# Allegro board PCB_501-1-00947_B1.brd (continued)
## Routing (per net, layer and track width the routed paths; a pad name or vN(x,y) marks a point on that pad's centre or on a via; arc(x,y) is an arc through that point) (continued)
DRAM_ADDR3: length 56.1
  TOP w0.102: U7.AC20 v2(62.59,95.84)
  TOP w0.137: U8.N2 v2(72.11,113.22) ; v2(54.95,113.22) 55.35,112.82 U9.N2
  L6_INT_2 w0.137: v2(54.95,113.22) 55.35,113.22 55.46,113.11 55.61,113.11 55.75,113.25 55.75,113.39 55.68,113.46 55.68,113.56 55.86,113.74 56.01,113.74 56.15,113.6 56.15,113.46 56.36,113.24 56.5,113.24 56.64,113.38 56.64,113.49 56.54,113.59 56.54,113.73 56.24,114.03 56.24,114.12 56.23,114.13 56.39,114.29 56.58,114.29 56.85,114.02 57.53,114.02 57.8,113.75 57.8,113.53 57.95,113.38 60.24,113.38 60.44,113.59 60.44,114.11 60.83,114.5 61.1,114.5 61.4,114.21 61.57,114.21 61.86,114.5 62.63,114.5 62.75,114.38 62.75,114.23 v2(62.91,114.06) 63.41,114.56 63.55,114.56 63.83,114.84 63.83,115.21 65.2,116.57 67.66,116.57 68.21,116.02 68.44,116.02 70.83,113.63 72,113.63 72.11,113.52 v2(72.11,113.22)
  BOTTOM w0.137: v2(62.59,95.84) 63.02,96.28 63.02,96.59 63.37,96.94 63.37,98.05 62.59,98.82 62.59,99.65 62.23,100.01 62.23,100.74 63.01,101.52 63.01,101.88 62.58,102.31 62.22,102.31 62.08,102.44 62.08,103.05 62.36,103.33 62.36,103.51 63.03,104.18 63.71,104.18 64.08,104.54 64.08,108.25 63.71,108.63 63.71,108.73 63.22,109.21 63.22,109.56 62.81,109.97 62.81,110.69 62.23,111.26 62.23,111.54 62.57,111.87 62.57,113.11 61.77,113.91 61.44,113.91 60.91,113.37 60.54,113.37 59.22,114.7 59.22,114.88 59.4,115.06 59.65,115.06 60.28,114.43 60.6,114.43 61.1,114.93 61.35,114.93 62.27,114.02 62.86,114.02 v2(62.91,114.06)
DRAM_ADDR4: length 61.1
  TOP w0.102: U7.AB21 v2(61.53,95.84)
  TOP w0.137: U9.P8 50.14,114.02 50.14,114.58 49.91,114.81 49.9,114.81 49.89,114.82 49.57,114.82 49.32,115.08 49.32,116.42 53.13,120.23 v2(61.23,120.23) 61.9,120.23 62.43,119.7 62.89,119.7 63.07,119.88 63.07,120.13 63.23,120.29 63.42,120.29 63.66,120.05 63.92,120.05 64.15,120.28 64.34,120.28 64.6,120.02 64.83,120.02 65.11,120.29 65.37,120.29 65.48,120.18 65.48,119.84 65.34,119.69 65.34,119.46 66.19,118.61 66.35,118.61 66.76,119.03 66.93,119.03 67.1,118.85 67.1,118.38 67.28,118.2 67.75,118.2 69.63,116.32 69.63,114.81 69.53,114.7 69.1,114.7 68.99,114.59 68.99,114.16 68.85,114.02 68.33,114.02 67.92,113.62 U8.P8
  L3_INT_1 w0.137: v2(61.23,120.23) 61.98,119.48 61.98,114.44 61.03,113.49 61.03,113.14 61.53,112.63 61.53,112.08 61.48,112.02 61.48,112.01 61.3,111.83 61.21,111.83 60.88,111.49 60.88,109.42 61.95,108.36 61.95,105.4 62.47,104.87 62.47,102.92 61.96,102.41 61.59,102.04 61.59,100.87 62.13,100.33 62.13,96.97 61.53,96.37 v2(61.53,95.84)
DRAM_ADDR5: length 57.8
  TOP w0.102: U7.Y23 v2(59.4,95.84)
  TOP w0.137: U8.P2 v2(72.11,114.02) ; U9.P2 v2(54.95,114.02)
  L3_INT_1 w0.137: v2(59.4,95.84) 59.4,96.55 59.92,97.07 59.92,99.89 59.8,100.01 59.63,100.01 59.51,99.89 59.51,97.43 59.39,97.31 59.22,97.31 59.1,97.43 59.1,100.05 59.45,100.4 59.72,100.4 59.92,100.6 59.92,102.15 60.15,102.37 60.15,102.55 59.86,102.84 59.86,103.35 60.09,103.58 60.09,103.77 59.78,104.07 59.78,104.27 60,104.48 60,104.66 59.88,104.78 59.83,104.78 59.71,104.9 59.71,105.07 59.83,105.19 59.88,105.19 60,105.31 60,105.48 59.88,105.6 59.83,105.6 59.71,105.72 59.71,105.89 59.83,106.01 59.88,106.01 60,106.13 60,106.4 59.89,106.51 59.89,106.65 59.77,106.76 59.77,106.96 60.02,107.2 60.02,107.46 59.75,107.73 59.75,108.41 59.89,108.55 59.89,108.75 59.71,108.94 59.71,112.04 59.87,112.21 59.87,112.69 59.71,112.85 59.71,114.5 60.15,114.94 60.15,114.95 60.23,115.03 v2(60.23,115.18)
  L6_INT_2 w0.137: v2(54.95,114.02) 55.21,114.02 56.04,114.84 56.27,114.84 56.39,114.96 56.39,115.16 56.06,115.49 56.06,115.87 56.16,115.97 56.38,115.97 56.64,115.71 56.78,115.71 56.94,115.87 56.94,116.01 56.72,116.23 56.72,116.41 56.87,116.55 57.02,116.55 57.26,116.31 57.48,116.31 57.56,116.4 57.56,116.51 57.67,116.62 57.83,116.62 58,116.44 58,115.87 57.45,115.32 57.45,115.18 57.56,115.07 57.76,115.07 58.07,115.38 58.2,115.38 58.3,115.29 58.3,115 57.96,114.66 57.96,114.52 58.07,114.4 58.24,114.4 58.46,114.63 58.66,114.63 58.8,114.49 58.8,114.3 58.93,114.17 59.37,114.17 59.5,114.3 59.5,114.5 59.37,114.63 59.27,114.63 59.15,114.75 59.15,114.89 59.32,115.06 59.71,115.06 59.9,114.88 60.09,114.88 60.23,115.01 v2(60.23,115.18) 60.33,115.28 62.06,115.28 64.14,117.36 68.13,117.36 70.96,114.52 71.6,114.52 v2(72.11,114.02)
DRAM_ADDR6: length 58.6
  TOP w0.102: U7.V22 v2(58.87,94.25)
  TOP w0.137: U8.R8 67.9,114.42 68.09,114.61 68.3,114.82 68.67,114.82 69.22,115.37 69.22,116.16 69.1,116.27 68.91,116.27 68.67,116.04 68.48,116.04 68.26,116.25 68.26,116.45 68.45,116.64 68.45,116.95 67.63,117.77 67.07,117.77 66.63,118.2 66.05,118.2 64.64,119.6 63.38,119.6 63.1,119.31 62.22,119.31 61.74,119.8 v2(60.59,119.8) 53.25,119.8 50.17,116.71 50.17,116.65 50.16,116.65 50.16,115.38 50.16,115.38 50.16,115.05 50.55,114.66 U9.R8
  L3_INT_1 w0.137: v2(60.59,119.8) 60.46,119.8 60.04,119.37 59.88,119.01 59.88,118.51 59.44,117.56 59.44,117.34 58.97,116.86 58.55,116.62 58.39,116.46 58.39,116.23 58.26,115.72 57.76,115.22 56.77,114.76 56.09,114.08 56.09,110 56.44,109.65 56.9,109.65 58,108.56 58,102.81 57.24,102.05 57.24,95.36 58.35,94.25 v2(58.87,94.25)
DRAM_ADDR7: length 59
  TOP w0.137: U9.R2 55.35,114.47 v2(54.98,114.84) ; U8.R2 v2(72.11,114.82) ; v2(59.93,95.31) U7.Y22
  L3_INT_1 w0.137: v2(59.68,115.88) 59.68,115.9 59.88,116.1 60.21,116.1 60.3,116.01 60.3,115.74 60.16,115.6 60.05,115.6 60.05,115.6 60.04,115.6 59.79,115.35 59.79,115.14 59.31,114.66 59.31,111.24 59.17,111.09 59.03,111.09 58.89,111.23 58.89,112.85 58.75,113 58.56,113 58.44,112.87 58.44,109.85 59.19,109.1 59.19,102.16 58.44,101.41 58.44,96.28 59.4,95.31 v2(59.93,95.31)
  L6_INT_2 w0.137: v2(54.98,114.84) 55.43,115.29 55.43,115.9 55.05,116.28 54.83,116.28 54.62,116.06 54.4,116.06 54.23,116.24 54.23,116.43 54.81,117.01 55.11,117.01 55.56,116.56 55.76,116.56 56.41,117.21 56.41,117.39 56.24,117.57 56.05,117.57 55.81,117.33 55.62,117.33 55.47,117.48 55.47,117.67 55.93,118.13 57.02,118.13 57.67,117.48 58.12,117.48 58.75,116.85 59,116.85 59.4,117.26 59.6,117.26 59.9,116.96 59.9,116.77 59.73,116.6 59.39,116.6 59.27,116.48 59.27,116.07 59.46,115.88 v2(59.68,115.88) 59.86,116.06 61.73,116.06 63.88,118.21 68.5,118.21 71.2,115.51 71.42,115.51 v2(72.11,114.82)
DRAM_ADDR8: length 55.5
  TOP w0.102: U7.W22 v2(59.4,94.78)
  TOP w0.137: U9.T8 50.55,116.49 53.36,119.3 60.13,119.3 v2(60.37,119.06) 60.53,118.9 63.56,118.9 64.27,118.19 64.47,118.19 64.59,118.31 64.59,118.45 64.14,118.9 64.14,119.14 64.21,119.21 64.48,119.21 65.88,117.81 66.47,117.81 66.9,117.38 67.47,117.38 67.81,117.04 67.81,116.2 68.04,115.97 68.04,115.55 U8.T8
  L3_INT_1 w0.137: v2(60.37,119.06) 60.37,118.79 60.53,118.63 60.53,118.5 60.2,118.17 60.2,117.53 59.36,116.69 59.36,116.22 59.19,116.05 59.19,115.11 58.89,114.81 58.89,113.6 58.68,113.39 58.52,113.39 58.23,113.68 58.23,113.85 58.47,114.09 58.47,114.49 58.38,114.57 58.24,114.57 57.92,114.25 57.92,114.16 57.61,113.84 57.61,113.65 58.05,113.21 58.05,112.49 57.71,112.15 57.71,111.72 58.05,111.38 58.05,110.15 57.92,110.03 57.92,109.81 58.8,108.93 58.8,102.32 58.05,101.57 58.05,95.6 58.87,94.78 v2(59.4,94.78)
DRAM_ADDR9: length 58.5
  TOP w0.102: U7.V23 v2(58.34,94.78)
  TOP w0.137: U8.R3 v2(71.12,115) ; U9.R3 v2(54.15,114.82)
  L3_INT_1 w0.137: v2(58.34,94.78) 57.64,95.49 57.64,101.9 57.74,102.01 57.74,102.02 58.41,102.68 58.41,108.74 57.12,110.03 57.12,110.21 56.81,110.52 56.53,110.52 56.45,110.6 56.45,110.84 56.54,110.93 57.35,110.93 57.51,111.09 57.51,111.3 57.34,111.48 56.62,111.48 56.45,111.65 56.45,112.27 56.59,112.42 57.45,112.42 57.58,112.55 57.58,113.01 57.38,113.22 56.58,113.22 56.43,113.36 56.43,113.76 56.69,114.02 57.31,114.02 57.58,114.29 57.58,114.47 58.4,115.29 v2(58.77,115.29)
  L6_INT_2 w0.137: v2(54.15,114.82) 53.69,114.82 53.45,114.57 52.95,114.57 52.23,115.29 52.05,115.29 51.32,114.56 51.32,114.37 51.46,114.23 51.64,114.23 52.06,114.66 52.26,114.66 52.77,114.14 53.67,114.14 53.94,114.42 55.19,114.42 55.75,114.98 55.75,116 56.77,117.02 57.98,117.02 58.37,116.63 58.37,116.08 58.77,115.69 v2(58.77,115.29) 58.93,115.45 59.9,115.45 60.12,115.67 61.89,115.67 63.99,117.77 68.35,117.77 v2(71.12,115)
DRAM_ADDR10: length 57.6
  TOP w0.102: U7.T23 57.28,93.72 v2(57.28,93.72)
  TOP w0.137: U8.L7 68.09,110.79 66.03,110.79 63.98,112.85 63.39,112.85 60.59,115.65 60.1,115.65 59.22,114.77 57.92,114.77 57.37,115.33 v2(57.37,115.9) 57.69,115.9 57.82,115.78 57.82,115.52 57.97,115.36 58.16,115.36 58.35,115.56 58.35,116.25 58.22,116.39 57,116.39 56.86,116.25 56.86,115.83 56.65,115.61 56.49,115.61 56.34,115.76 56.34,116.14 56.08,116.41 55.89,116.41 55.75,116.26 55.57,116.26 55.39,116.44 53.83,116.44 53.34,115.95 53.34,114.03 53.11,113.8 53.11,113.51 53.27,113.35 53.27,113.14 U9.L7
  L3_INT_1 w0.137: v2(57.28,93.72) 57.03,93.98 56.34,93.98 56.06,94.26 56.06,94.69 56.43,95.07 56.43,102.32 57.2,103.09 57.2,108.06 57.04,108.22 56.4,108.22 55.41,109.2 55.41,116.37 55.62,116.58 56.31,116.58 56.43,116.46 56.43,116.35 56.55,116.23 56.72,116.23 56.84,116.35 56.84,116.46 56.96,116.58 57.23,116.58 57.37,116.45 v2(57.37,115.9)
DRAM_ADDR11: length 54.7
  TOP w0.102: v2(58.34,93.72) 58.34,93.19 U7.U22
  TOP w0.137: U8.R7 68.31,114.42 67.91,114.02 66.75,114.02 65.72,115.05 65.72,115.77 64.09,117.41 63.95,117.41 63.32,118.04 61.14,118.04 61.14,118.04 60.79,118.04 60.79,118.04 60.04,118.04 v2(59.43,118.65) 59.31,118.78 53.52,118.78 51.46,116.71 51.46,116.06 51.78,115.75 51.78,114.84 U9.R7
  L3_INT_1 w0.137: v2(59.43,118.65) 58.94,118.16 58.94,117.96 59.05,117.85 59.05,117.5 58.81,117.25 58.18,117.25 57.89,116.96 57.89,115.83 57.55,115.49 57.19,115.49 56.87,115.81 56.4,115.81 56.13,116.08 55.92,116.08 55.79,115.94 55.79,109.33 56.5,108.61 57.19,108.61 57.58,108.22 57.58,103.04 56.85,102.31 56.85,94.69 57.81,93.72 v2(58.34,93.72)
DRAM_ADDR12: length 55.7
  TOP w0.102: U7.T22 v2(57.81,93.19)
  TOP w0.137: U8.N7 68.12,113.21 66.36,113.21 65.77,113.8 65.57,113.8 65.23,114.14 65.23,114.75 62.33,117.65 61.3,117.65 60.63,117.65 58.65,117.65 v2(58.63,117.68) 58.26,117.68 58.16,117.58 57.6,117.58 57.36,117.83 57.36,118.19 57.16,118.39 53.69,118.38 51.92,116.62 51.92,116.17 52.12,115.97 52.12,114.55 51.78,114.21 51.78,113.25 U9.N7
  L3_INT_1 w0.137: v2(57.81,93.19) 57.28,93.19 56.92,93.55 56.92,93.55 56.91,93.56 56.28,93.56 55.61,94.24 55.61,94.74 56.02,95.16 56.02,102.81 56.16,102.95 56.16,107.81 55.11,108.86 54.74,108.86 54.28,109.33 54.28,109.47 54.55,109.75 54.55,116.07 55.5,117.02 57.24,117.02 57.8,117.58 57.96,117.58 58.24,117.87 58.44,117.87 v2(58.63,117.68)
DRAM_ADDR13: length 57
  TOP w0.102: U7.P23 v2(56.22,92.66)
  TOP w0.137: U8.T3 71.36,115.57 v2(71.36,116.03) ; U9.T3 v2(54.15,115.62)
  L6_INT_2 w0.137: v2(54.15,115.62) 53.91,115.86 53.77,115.86 53.4,115.49 53.22,115.49 53.06,115.65 53.06,115.81 55.77,118.52 58.41,118.52 59.28,117.65 59.86,117.65 60.98,116.53 v2(61.55,116.53) 63.62,118.6 68.79,118.6 71.36,116.03 v2(71.36,116.03)
  BOTTOM w0.137: v2(61.55,116.53) 61.55,117.21 60.67,118.09 59.63,118.09 57.92,116.38 57.92,115.84 57.51,115.44 57.51,111.74 57.06,111.29 57.06,109.8 58.19,108.66 58.19,102.65 56.29,100.74 56.29,94.74 55.68,94.14 55.68,93.2 v2(56.22,92.66)
DRAM_ADDR14: length 56.8
  TOP w0.102: U7.AB18 v2(63.12,94.23)
  TOP w0.137: U8.T7 68.26,115.22 67.88,114.83 67.87,114.82 67.55,114.82 67.54,114.83 67.53,114.83 67.31,115.05 67.31,115.59 67.53,115.81 67.53,116.05 67.41,116.17 67.41,116.64 67.24,116.8 67.1,116.8 66.39,116.09 66.09,116.09 65.88,116.3 65.88,116.6 66.05,116.76 66.35,116.76 66.51,116.93 66.51,117.13 66.22,117.42 65.71,117.42 65.11,118.02 64.85,118.02 64.63,117.8 64.11,117.8 63.45,118.47 v2(60.96,118.47) ; U9.T7 v2(50.95,114.81)
  L6_INT_2 w0.137: v2(50.95,114.81) 55.45,119.31 59.49,119.31 60.33,118.47 v2(60.96,118.47)
  BOTTOM w0.137: v2(63.12,94.23) 63.12,94.78 63.8,95.46 63.8,95.84 64.35,96.4 64.35,98.18 65.02,98.84 65.02,109.26 64.21,110.07 64.21,110.55 63.56,111.2 63.56,112.62 64.21,113.26 64.21,114.14 63.83,114.52 63.14,114.52 63.13,114.52 62.32,114.52 61.46,115.38 61.05,115.38 60.53,115.9 60.53,116.05 60.83,116.35 61.01,116.35 61.44,115.92 61.7,115.92 62.14,116.37 62.14,117.29 v2(60.96,118.47)
DRAM_ADDR15: length 56
  TOP w0.102: U7.AB20 62.06,95.3 62.04,95.31 62.04,95.32 v2(62.05,95.32)
  TOP w0.137: U8.M7 68.26,112.02 67.86,111.61 65.99,111.61 64.46,113.13 64.46,114.4 64.02,114.84 63.85,114.84 63.53,114.52 63.17,114.52 62.92,114.77 62.92,115.24 62.69,115.46 62.69,116.07 62.55,116.21 62.14,116.21 62,116.07 62,115.83 61.87,115.7 61.66,115.7 61.03,116.34 60.45,116.34 v2(60.26,116.53) 60.01,116.78 56.32,116.78 56.28,116.83 53.67,116.83 52.95,116.11 52.95,114.23 52.54,113.82 52.54,112.83 51.72,112.02 U9.M7
  L3_INT_1 w0.137: v2(60.26,116.53) 60.08,116.71 60.08,116.85 60.28,117.05 60.42,117.05 60.74,116.74 60.74,116.12 60.89,115.97 60.89,115.85 60.69,115.65 60.69,114.93 60.1,114.34 60.1,113.01 60.26,112.85 60.26,112.04 60.1,111.88 60.1,109.1 60.45,108.75 60.45,108.55 60.14,108.25 60.14,107.9 60.57,107.46 60.57,107.19 60.28,106.89 60.28,106.67 60.57,106.37 60.57,106.14 60.39,105.95 60.39,104.44 60.73,104.09 60.73,103.78 61.04,103.47 61.25,103.47 61.43,103.29 61.43,103.19 61.15,102.91 60.95,102.91 60.53,103.33 60.39,103.33 60.25,103.19 60.25,103 60.76,102.49 60.76,102.26 60.62,102.12 60.45,102.12 60.31,101.98 60.31,101.71 60.45,101.57 60.62,101.57 60.76,101.43 60.76,101.16 60.62,101.02 60.45,101.02 60.31,100.89 60.31,100.61 60.45,100.47 60.62,100.47 60.76,100.34 60.76,100.06 60.62,99.93 60.45,99.93 60.31,99.79 60.31,99.51 60.45,99.38 60.53,99.38 60.67,99.24 60.67,99.01 60.53,98.88 60.36,98.88 60.22,98.74 60.22,98.49 60.36,98.35 60.65,98.35 60.82,98.19 60.82,97.95 60.68,97.82 60.55,97.82 60.37,97.64 60.37,97.53 60.84,97.06 60.84,96.74 60.62,96.52 60.62,96.22 61.52,95.32 v2(62.05,95.32)
DRAM_CAS_B: length 53.7
  TOP w0.104: U7.AC14 v2(65.77,92.66)
  TOP w0.137: U8.K3 v2(71.31,110.82) ; U9.K3 v2(54.15,110.82)
  L3_INT_1 w0.137: v2(65.77,92.66) 65.77,93.52 65.49,93.81 65.49,95.75 64.82,96.42 64.82,101.75 65.56,102.49 65.56,105.81 65.77,106.02 65.77,108.48 66.9,109.61 66.9,112.23 66.54,112.58 66.33,112.58 66.17,112.74 66.17,113.42 65.81,113.78 65.27,113.78 65.07,113.98 65.07,114.23 65.23,114.39 65.23,114.62 65.02,114.84 65.02,115.15 65.23,115.36 65.23,115.59 65.1,115.72 64.63,115.72 64.5,115.59 64.5,111.16 v2(63.36,110.02)
  L6_INT_2 w0.137: v2(54.15,110.82) U9.K3 55.83,110.42 55.95,110.53 56.88,110.53 57.35,110.07 57.6,110.07 57.89,109.78 60.45,109.78 60.53,109.85 62.8,109.85 62.97,110.02 v2(63.36,110.02) 64.1,110.77 64.49,110.77 65.33,111.61 66.58,111.61 66.83,111.86 66.83,112.14 67.04,112.35 67.35,112.35 67.73,111.97 68.27,111.97 69.04,111.2 69.8,111.2 70.19,110.82 v2(71.31,110.82)
DRAM_CS0_B: length 56.1
  TOP w0.137: U7.AB23 v2(60.46,96.9) ; U8.L2 v2(72.11,111.62) ; v2(54.95,111.62) 55.51,111.62 55.75,111.38 55.75,110.87 55.66,110.78 55.52,110.78 55.35,110.95 U9.L2
  L6_INT_2 w0.137: v2(72.11,111.62) 71.71,112.02 70.39,112.02 68.85,113.55 65.45,113.55 64.02,112.12 62.8,112.12 62.3,111.61 61.69,111.61 v2(61.41,111.34) 60.94,111.81 58.44,111.81 58.32,111.68 58.32,111.5 58.43,111.39 59.15,111.39 59.29,111.26 59.29,111.12 59.15,110.98 58.23,110.98 57.96,111.25 57.96,111.66 57.88,111.74 57.76,111.74 57.24,111.21 56.74,111.21 56.24,111.72 56.04,111.72 55.95,111.63 55.95,111.37 55.81,111.23 55.57,111.23 55.43,111.38 55.43,111.51 55.3,111.64 54.98,111.64 v2(54.95,111.62)
  BOTTOM w0.137: v2(60.46,96.9) 59.76,96.9 58.17,95.32 57.91,95.32 57.49,95.73 57.49,99.85 59.7,102.05 59.7,109.08 58.78,110 58.78,111.61 59.48,112.3 59.67,112.3 59.81,112.17 59.81,111.97 59.25,111.41 59.25,111.22 59.44,111.02 59.64,111.02 60.22,111.6 60.41,111.6 60.56,111.46 60.56,111.26 59.91,110.61 59.51,110.21 59.51,110.02 59.71,109.82 59.9,109.82 v2(61.41,111.34)
DRAM_CS1_B: length 57.2
  TOP w0.102: U7.AA22 v2(60.46,95.84)
  TOP w0.137: U9.L1 56.52,111.22 56.54,111.2 57.83,111.2 58.12,111.48 58.12,112.69 57.98,112.83 57.64,112.83 57.47,112.99 57.47,113.46 57.75,113.73 58.57,113.73 58.7,113.61 58.7,111.45 57.73,110.48 v2(57.56,110.48) ; U8.L1 v2(72.91,111.62)
  L6_INT_2 w0.137: v2(72.91,111.62) 72.91,111.6 72.52,111.21 70.29,111.21 68.68,112.83 66.53,112.83 65.84,112.13 65.18,112.13 64.36,111.31 63.29,111.31 62.81,110.83 62.13,110.83 61.75,110.44 v2(61.32,110.44) 61.05,110.44 60.51,110.99 60.27,110.99 59.46,110.17 57.87,110.17 v2(57.56,110.48)
  BOTTOM w0.137: v2(61.32,110.44) 60.1,109.22 60.1,109 60.28,108.82 60.41,108.82 61.81,110.22 61.9,110.22 62.15,109.97 62.15,109.83 60.88,108.56 60.88,108.38 61.1,108.16 61.3,108.16 61.43,108.29 61.68,108.29 61.99,107.98 61.99,107.71 61.87,107.6 61.87,107.43 62,107.31 62.19,107.31 62.31,107.19 62.31,107.02 62.19,106.9 62,106.9 61.87,106.78 61.87,106.61 62,106.49 62.19,106.49 62.31,106.37 62.31,106.2 62.19,106.08 62,106.08 61.87,105.96 61.87,105.79 62,105.67 62.19,105.67 62.31,105.54 62.31,104.68 62.04,104.41 61.78,104.41 61.58,104.2 61.58,103.78 61.33,103.53 60.98,103.53 60.74,103.29 60.74,102.79 60.86,102.67 61.18,102.67 61.3,102.55 61.3,102.38 61.18,102.26 60.86,102.26 60.74,102.14 60.74,101.63 60.35,101.23 60.35,100.73 60.56,100.51 60.56,100.1 60.44,99.97 60.44,99.52 60.82,99.15 60.82,98.82 60.46,98.47 60.46,97.99 60.59,97.86 60.77,97.86 61.05,98.14 61.05,98.32 61.23,98.5 61.37,98.5 61.55,98.32 61.55,98.03 61.35,97.83 61.35,97.69 61.52,97.53 61.66,97.53 61.96,97.83 62.14,97.83 62.38,97.6 62.38,97.39 62.04,97.04 62.04,96.89 60.99,95.84 v2(60.46,95.84)
DRAM_DATA0: length 13.5
  TOP w0.137: U8.D7 68.59,105.69 68.87,105.69 69.01,105.56 69.01,105.38 68.87,105.24 68.66,105.24 68.37,105.24 68.1,104.97 68.1,103.82 67.9,103.62 66.53,103.62 65.83,102.92 65.83,102.52 66.13,102.22 66.13,102.11 63.11,99.09 63.11,98.5 62.06,97.44 U7.AD22
DRAM_DATA1: length 11.8
  TOP w0.137: U8.C8 67.31,105.22 66.11,105.22 64.46,103.56 64.46,103.02 64.91,102.58 64.91,102.29 63.3,100.68 63.3,100.38 62.3,99.37 62.3,98.74 61.98,98.42 61.53,97.96 U7.AD23 arc(61.53,97.43) 61.52,97.43
DRAM_DATA2: length 13.1
  TOP w0.137: 70.46,103.57 70.46,102.59 68.13,100.26 67.53,100.26 U7.AE20 ; 70.46,103.57 71.15,104.26 ; 70.46,103.57 71.15,104.26 ; 71.15,104.26 U8.C3
DRAM_DATA3: length 11.7
  TOP w0.137: U7.AE23 62.7,98.61 62.7,99.27 63.67,100.24 63.67,100.52 63.81,100.67 64.1,100.67 64.25,100.82 64.25,101.11 64.4,101.25 64.68,101.25 64.83,101.4 64.83,101.69 64.98,101.83 65.26,101.83 65.48,102.05 65.48,102.61 64.93,103.16 64.93,103.31 65.23,103.62 65.38,103.62 65.59,103.4 65.77,103.4 65.95,103.59 65.95,103.73 65.72,103.96 65.72,104.14 65.99,104.41 67.32,104.41 U8.B8
DRAM_DATA4: length 11.9
  TOP w0.137: U8.A7 68.78,103.22 68.92,103.35 68.92,103.54 68.84,103.62 68.35,103.62 68.11,103.38 68.11,103.02 68.25,102.88 68.25,102.68 67.91,102.34 67.91,102.14 67.81,102.04 67.35,102.04 66.89,102.5 66.74,102.5 66.54,102.31 66.54,102.2 66.76,101.98 66.76,101.8 66.61,101.66 66.16,101.66 65.63,101.14 65.63,100.99 65.47,100.82 65.32,100.82 64.8,100.3 64.8,100.14 64.64,99.98 64.48,99.98 63.59,99.1 63.59,98.44 U7.AE22
DRAM_DATA5: length 12
  TOP w0.137: U8.A3 71.15,103.22 70.8,102.86 70.8,102.31 68.32,99.83 67.63,99.83 64.84,97.04 63.65,95.84 U7.AD19
DRAM_DATA6: length 12.4
  TOP w0.137: U7.AD18 64.18,95.33 65.9,97.05 TP15.1 67.96,99.07 68.8,99.07 TP16.1 72.51,102.78 U8.A2
DRAM_DATA7: length 12.9
  TOP w0.137: U7.AE19 67.78,99.45 68.57,99.45 72.12,102.99 72.12,104.42 U8.C2
DRAM_DATA8: length 18
  TOP w0.137: U8.E3 71.36,106.07 v2(71.29,106.07) ; v2(70.15,96.9) 70.15,96.37 68.47,94.68 68.32,94.68 67.94,94.31 U7.AE14
  L3_INT_1 w0.137: v2(70.15,96.9) 69.82,97.23 69.82,97.9 69.94,98.02 70.18,98.02 70.3,98.14 70.3,98.31 70.18,98.43 69.94,98.43 69.82,98.55 69.82,98.81 70.06,99.05 70.23,99.05 70.4,98.89 70.57,98.89 70.69,99.01 70.69,99.18 70.52,99.34 70.52,99.51 70.64,99.64 70.82,99.64 70.98,99.47 71.15,99.47 71.27,99.59 71.27,99.76 71.11,99.93 71.11,100.1 71.37,100.36 71.37,102.95 71.77,103.35 71.77,104.02 71.29,104.5 v2(71.29,106.07)
DRAM_DATA9: length 18.1
  TOP w0.137: v2(68.1,108.4) 68.1,108.42 U8.H8 ; v2(65.68,96.22) 64.77,95.31 U7.AE18
  L3_INT_1 w0.137: v2(65.68,96.22) 65.68,97 66.01,97.34 66.01,100.05 66.25,100.29 67.4,100.29 67.65,100.54 67.65,101.42 67.53,101.54 66.98,101.54 66.86,101.66 66.86,101.83 66.98,101.95 67.53,101.95 67.67,102.09 67.67,102.92 67.39,103.21 66.93,103.21 66.8,103.34 66.8,107.05 66.77,107.07 v2(68.1,108.4)
DRAM_DATA10: length 17.8
  TOP w0.137: U7.AE17 65.24,95.12 66.38,96.26 66.38,96.72 v2(66.39,96.72) ; U8.F8 v2(67.32,106.83)
  L3_INT_1 w0.137: v2(66.39,96.72) 66.38,96.73 66.38,99.61 66.52,99.75 66.86,99.75 67,99.6 67,98.36 67.15,98.21 67.35,98.21 67.52,98.39 67.52,99.8 68.36,100.64 68.36,100.93 68.02,101.27 68.02,103.07 67.19,103.9 67.19,106.69 v2(67.32,106.83)
DRAM_DATA11: length 17.9
  TOP w0.137: v2(66.96,95.28) 66.96,94.91 65.77,93.72 U7.AD16 arc(65.24,93.72) 65.24,93.72 ; U8.H7 v2(69,108.33)
  L3_INT_1 w0.137: v2(69,108.33) 69.6,107.73 69.6,100.2 68.68,99.29 68.68,97.46 68.18,96.95 67.8,96.95 66.96,96.11 v2(66.96,95.28)
DRAM_DATA12: length 17.9
  TOP w0.137: U8.F7 v2(68.9,106.82) ; v2(66.26,94.91) 66.26,94.74 U7.AE16
  L3_INT_1 w0.137: v2(68.9,106.82) 69.26,106.47 69.26,106.05 69.14,105.93 68.99,105.93 68.87,105.81 68.87,105.64 68.99,105.52 69.14,105.52 69.26,105.4 69.26,105.23 69.14,105.11 68.99,105.11 68.87,104.99 68.87,104.81 68.99,104.69 69.14,104.69 69.26,104.57 69.26,104.4 69.14,104.28 68.99,104.28 68.87,104.16 68.87,103.99 68.99,103.87 69.14,103.87 69.26,103.75 69.26,103.58 69.14,103.46 68.99,103.46 68.87,103.34 68.87,103.17 68.99,103.05 69.14,103.05 69.26,102.93 69.26,102.76 69.14,102.64 68.99,102.64 68.87,102.52 68.87,102.35 68.99,102.23 69.14,102.23 69.26,102.1 69.26,101.93 69.14,101.81 68.99,101.81 68.87,101.69 68.87,101.52 68.99,101.4 69.14,101.4 69.26,101.28 69.26,100.34 68.34,99.43 68.34,97.67 68.03,97.36 67.67,97.36 66.26,95.95 v2(66.26,94.91)
DRAM_DATA13: length 19.1
  TOP w0.137: v2(70.77,97.44) 70.77,96.49 68.65,94.38 68.55,94.38 66.83,92.66 U7.AD14 ; v2(72.11,106.85) 72.11,108.41 U8.H3
  L3_INT_1 w0.137: v2(70.77,97.44) 70.77,98.53 71.81,99.57 71.81,102.86 72.11,103.17 v2(72.11,106.85)
DRAM_DATA14: length 19.2
  TOP w0.137: v2(71.93,98.59) 71.93,96.8 68.48,93.34 68.48,93.27 67.34,92.13 U7.AD13 ; U8.G2 72.88,107.64 v2(72.88,107.64)
  L3_INT_1 w0.137: v2(72.88,107.64) 73.32,107.2 73.32,103.22 72.94,102.84 72.94,99.59 v2(71.93,98.59)
DRAM_DATA15: length 18.1
  TOP w0.137: U7.AE13 71.32,96.62 v2(71.32,98.05) ; U8.F2 72.51,107.21 v2(72.91,106.81)
  L3_INT_1 w0.137: v2(71.32,98.05) 71.32,98.61 72.48,99.76 72.48,100.61 72.36,100.73 72.28,100.73 72.16,100.85 72.16,101.02 72.28,101.14 72.36,101.14 72.48,101.27 72.48,101.44 72.36,101.56 72.28,101.56 72.16,101.68 72.16,101.85 72.28,101.97 72.36,101.97 72.48,102.09 72.48,102.26 72.36,102.38 72.28,102.38 72.16,102.5 72.16,102.67 72.28,102.79 72.36,102.79 72.48,102.91 72.48,105.86 72.48,106.38 v2(72.91,106.81)
DRAM_DATA16: length 11.8
  TOP w0.137: U9.D7 52.24,104.72 52.62,104.35 53.18,103.78 53.18,102.77 58.15,97.8 58.15,97.63 U7.AA25
DRAM_DATA17: length 13
  TOP w0.137: U9.C8 50.95,104.41 50.95,103.05 50.97,103.03 50.97,102.83 50.97,102.82 50.97,102.62 55.97,97.62 55.97,97.32 57.33,95.97 57.33,95.8 57.82,95.31 U7.W24
DRAM_DATA18: length 12.3
  TOP w0.137: U7.V25 56.92,95.68 56.92,95.9 55.63,97.18 55.63,97.34 54.56,98.42 54.37,98.42 TP18.1 TP17.1 50.71,102.08 50.28,102.08 50.06,102.3 50.06,102.87 50.16,102.97 50.16,103.62 U9.B8
DRAM_DATA19: length 11.1
  TOP w0.137: U9.A7 51.35,102.86 51.56,102.66 51.91,102.66 52.05,102.52 52.05,102.1 56.56,97.59 56.56,97.46 56.5,97.4 56.5,97.23 56.62,97.11 56.79,97.11 56.87,97.2 57.04,97.2 57.16,97.08 57.16,96.91 57.08,96.82 57.08,96.65 57.2,96.53 57.37,96.53 57.46,96.61 57.63,96.61 57.81,96.43 U7.W25
DRAM_DATA20: length 11.1
  TOP w0.137: U9.A2 55.75,103.62 55.75,104.23 55.94,104.42 56.58,104.42 56.58,104.42 56.94,104.42 57.17,104.19 57.17,103.01 56.8,102.64 56.8,102.37 57.13,102.04 57.42,102.04 57.57,101.89 57.57,101.6 57.72,101.45 58,101.45 58.15,101.31 58.15,101.02 58.3,100.87 58.58,100.87 58.73,100.73 58.73,100.44 58.88,100.29 59.17,100.29 59.31,100.14 59.31,99.86 59.54,99.63 59.54,98.36 U7.AC25
DRAM_DATA21: length 11
  TOP w0.137: U7.AB25 58.88,97.95 58.88,98.14 58.82,98.21 58.82,98.5 58.67,98.65 58.38,98.65 58.24,98.79 58.24,99.08 58.09,99.23 57.8,99.23 57.66,99.37 57.66,99.66 57.51,99.81 57.22,99.81 57.07,99.95 57.07,100.25 56.93,100.39 56.64,100.39 56.49,100.54 56.49,100.83 56.35,100.97 56.06,100.97 55.91,101.12 55.91,101.41 55.77,101.56 55.47,101.56 55.33,101.7 55.33,101.99 55.18,102.14 54.89,102.14 54.01,103.02 54.01,104.28 U9.C3
DRAM_DATA22: length 11.5
  TOP w0.137: U7.AB24 59.93,97.43 59.22,98.15 59.22,98.71 58.89,99.04 58.89,99.21 58.99,99.31 58.99,99.48 58.87,99.6 58.7,99.6 58.6,99.5 58.43,99.5 58.31,99.62 58.31,99.79 58.41,99.89 58.41,100.06 58.29,100.18 58.12,100.18 58.02,100.08 57.85,100.08 57.73,100.2 57.73,100.37 57.83,100.47 57.83,100.64 57.71,100.76 57.54,100.76 57.44,100.66 57.27,100.66 57.15,100.78 57.15,100.96 57.24,101.05 57.24,101.22 57.12,101.35 56.95,101.35 56.86,101.25 56.68,101.25 56.56,101.37 56.56,101.54 56.66,101.64 56.66,101.81 56.54,101.93 56.37,101.93 56.27,101.83 56.1,101.83 55.98,101.95 55.98,102.12 56.08,102.22 56.08,102.39 55.96,102.51 55.79,102.51 55.69,102.41 55.52,102.41 55.21,102.72 55.05,102.72 U9.A3
DRAM_DATA23: length 11
  TOP w0.137: U9.C2 55.77,105.23 56.97,105.23 57.31,104.89 57.31,104.64 57.58,104.37 57.58,102.4 59.9,100.08 59.9,98.52 60.46,97.95 60.46,97.79 U7.AC24
DRAM_DATA24: length 18.2
  TOP w0.102: v2(54.49,94.73) 55.5,93.72 U7.R25
  TOP w0.137: U9.E3 54.14,106 54.14,105.6 v2(53.29,104.75)
  L3_INT_1 w0.137: v2(53.29,104.75) 52.93,104.39 52.93,104.13 53.05,104.01 53.1,104.01 53.22,103.89 53.22,103.72 53.1,103.6 53.05,103.6 52.93,103.47 52.93,103.3 53.05,103.18 53.1,103.18 53.22,103.06 53.22,102.89 53.1,102.77 53.05,102.77 52.93,102.65 52.93,102.48 53.05,102.36 53.1,102.36 53.22,102.24 53.22,102.07 53.1,101.95 53.05,101.95 52.93,101.83 52.93,101.13 52.75,100.95 52.75,100.79 52.93,100.61 52.93,99.87 52.81,99.75 52.81,99.47 52.93,99.35 52.93,98.8 53.1,98.63 53.36,98.63 53.49,98.5 53.49,98.23 53.37,98.11 53.37,97.9 53.57,97.69 53.57,97.22 53.23,96.88 53.23,96.72 53.51,96.45 53.65,96.45 53.78,96.58 53.97,96.58 54.09,96.46 54.09,96.26 53.68,95.85 53.68,95.67 53.83,95.52 54.01,95.52 54.33,95.83 54.52,95.83 54.64,95.71 54.64,95.5 54.25,95.11 54.25,94.97 v2(54.49,94.73)
DRAM_DATA25: length 19.9
  TOP w0.102: U7.N24 54.62,92.13 54.15,92.6 54.15,92.67 53.51,93.31 53.02,93.31 52.76,93.57
  TOP w0.137: 52.76,93.57 v2(52.57,93.76) ; U9.H8 v2(50.12,108.38)
  L3_INT_1 w0.137: v2(52.57,93.76) 49.67,96.65 49.67,107.94 v2(50.12,108.38)
DRAM_DATA26: length 18.5
  TOP w0.102: v2(53.73,94.35) 54.57,93.51 54.84,93.51 U7.P25
  TOP w0.137: U9.H7 51.33,108.82 v2(50.95,108.43)
  L3_INT_1 w0.137: v2(50.95,108.43) 51.48,107.89 51.48,107.09 51.93,106.64 51.93,105.95 51.38,105.4 51.38,102.31 50.92,101.85 50.92,97.17 v2(53.73,94.35)
DRAM_DATA27: length 18.2
  TOP w0.102: U7.N25 53.66,93.63 53.26,93.63 v2(53.21,93.69)
  TOP w0.137: U9.F8 v2(50.17,107.59)
  L3_INT_1 w0.137: v2(53.21,93.69) 53.21,93.7 50.07,96.83 50.07,104.48 50.62,105.03 50.62,105.67 50.9,105.95 50.9,106.14 50.54,106.49 50.54,107.22 v2(50.17,107.59)
DRAM_DATA28: length 18.1
  TOP w0.137: v2(54.53,97.87) 54.53,97.17 55.62,96.07 55.82,96.07 56.28,95.62 56.28,95.25 U7.U25 ; v2(54.95,107.57) 55.35,107.98 U9.G2
  L3_INT_1 w0.137: v2(54.53,97.87) 54.25,98.15 54.25,98.71 53.61,99.34 53.61,99.7 53.73,99.82 53.94,99.82 54.06,99.95 54.06,100.12 53.94,100.24 53.73,100.24 53.61,100.36 53.61,100.53 53.73,100.65 53.94,100.65 54.06,100.77 54.06,100.94 53.94,101.06 53.73,101.06 53.61,101.18 53.61,101.44 54.11,101.94 54.11,105.19 54.18,105.26 54.18,105.69 54.48,106 54.48,106.97 53.88,107.57 53.88,107.71 54.05,107.88 54.23,107.88 54.65,107.47 54.84,107.47 v2(54.95,107.57)
DRAM_DATA29: length 18.2
  TOP w0.102: U7.R24 55.69,93.19 55.34,93.54 55.16,93.54 54.07,94.63 54.03,94.63 53.92,94.74
  TOP w0.137: 53.92,94.74 v2(53.72,94.94) ; U9.F7 v2(51.94,107.22)
  L3_INT_1 w0.137: v2(51.94,107.22) 52.12,107.22 52.28,107.05 52.28,105.84 51.78,105.34 51.78,102.23 51.26,101.71 51.26,97.4 51.57,97.08 51.74,97.08 51.75,97.09 51.92,97.09 52.04,96.97 52.04,96.8 52.04,96.79 52.04,96.62 52.9,95.76 53.18,95.76 53.33,95.61 53.33,95.33 v2(53.72,94.94)
DRAM_DATA30: length 19
  TOP w0.137: v2(53.96,108.44) 54.17,108.44 U9.H3 ; v2(54.69,96.34) 55.27,95.77 55.75,95.77 55.98,95.54 55.98,95.02 56.13,94.88 56.75,94.25 U7.U24
  L3_INT_1 w0.137: v2(53.96,108.44) 53.89,108.44 53.64,108.69 53.44,108.69 53,108.25 53,108.06 54.03,107.04 54.03,106.1 53.85,105.92 53.85,105.34 53.72,105.22 53.72,102.04 53.27,101.59 53.27,99.2 53.91,98.57 53.91,97.88 54.69,97.1 v2(54.69,96.34)
DRAM_DATA31: length 18.2
  TOP w0.137: U9.F2 55.35,107.22 v2(54.96,106.82) ; U7.V24 57.28,94.78 56.79,95.28 56.59,95.47 56.59,95.74 v2(55.16,97.17)
  L3_INT_1 w0.137: v2(54.96,106.82) 54.94,106.8 54.94,105.89 54.49,105.45 54.49,104.96 54.63,104.82 55.18,104.82 55.38,104.61 55.38,103.47 55.09,103.17 54.63,103.17 54.49,103.03 54.49,102.85 54.9,102.44 54.9,102.25 54.14,101.49 54.14,101.34 54.28,101.2 54.69,101.2 54.78,101.11 54.78,100.83 54.64,100.69 54.48,100.69 54.33,100.55 54.33,100.35 54.47,100.21 54.63,100.21 54.76,100.08 54.76,99.71 54.63,99.58 54.37,99.58 54.17,99.38 54.17,99.27 54.59,98.85 54.59,98.38 54.75,98.22 54.96,98.22 55.09,98.09 55.09,97.84 54.87,97.62 54.87,97.46 v2(55.16,97.17)
DRAM_DQM0: length 13.7
  TOP w0.137: U8.D3 71.06,104.96 70,103.91 70,102.69 68.14,100.83 67.58,100.83 63.12,96.37 U7.AD20
DRAM_DQM1: length 18.9
  TOP w0.137: U7.AD17 65.24,94.25 65.7,94.71 65.7,94.99 67.01,96.31 v2(67.01,97.39) ; U8.E7 v2(68.1,106.83)
  L3_INT_1 w0.137: v2(68.1,106.83) 67.62,106.36 67.62,105.79 67.8,105.61 68.3,105.61 68.48,105.44 68.48,105.17 68.36,105.05 67.82,105.05 67.7,104.93 67.7,104.76 67.82,104.64 68.36,104.64 68.48,104.52 68.48,104.35 68.36,104.23 67.82,104.23 67.7,104.11 67.7,103.94 67.82,103.82 68.36,103.82 68.48,103.7 68.48,101.36 68.81,101.03 68.81,100.51 67.95,99.65 67.95,98.04 67.7,97.79 67.42,97.79 v2(67.01,97.39)
DRAM_DQM2: length 12
  TOP w0.137: U7.AA24 59.4,96.88 58.51,97.78 58.51,97.99 53.59,102.9 53.59,104.44 54.55,105.4 U9.D3
DRAM_DQM3: length 18.1
  TOP w0.102: 53.34,94.16 53.57,93.93 53.76,93.93 54.68,93.01 54.81,93.01 55.16,92.66 U7.P24
  TOP w0.137: U9.E7 50.98,106.79 v1(50.97,106.79) ; v2(53.14,94.36) 53.34,94.16
  L3_INT_1 w0.137: v1(50.97,106.79) 50.98,106.79 51.22,106.54 51.47,106.54 51.61,106.41 51.61,106.11 50.98,105.48 50.98,102.4 50.58,101.99 50.58,96.92 v2(53.14,94.36)
DRAM_ODT0: length 54.5
  TOP w0.102: U7.AC16 64.71,93.72 v2(64.71,93.72)
  TOP w0.137: U8.K1 v2(72.91,110.82) ; v2(56.65,110.08) 56.93,110.08 57.1,110.25 57.1,110.64 56.94,110.8 56.26,110.8 56.15,110.69 U9.K1
  L3_INT_1 w0.137: v2(64.71,93.72) 64.84,93.85 64.84,95.3 64,96.13 64,102.02 63.64,102.38 63.64,104.89 63.78,105.04 63.96,105.04 64.08,104.91 64.08,102.76 64.26,102.58 64.47,102.58 64.6,102.71 64.6,105.4 64.47,105.54 63.48,105.54 63.12,105.9 63.12,107.33 63.26,107.46 63.45,107.46 63.53,107.39 63.53,106.16 63.72,105.97 64.54,105.97 64.68,106.11 64.68,106.35 64.54,106.49 64.12,106.49 63.99,106.62 63.99,106.82 64.11,106.94 64.64,106.94 64.78,107.08 64.78,107.27 64.65,107.41 64.14,107.41 63.99,107.55 63.99,107.75 64.13,107.89 64.72,107.89 64.86,108.03 64.86,108.24 64.72,108.38 63.8,108.38 63.66,108.51 63.66,108.83 63.52,108.97 63.31,108.97 63.15,109.13 63.15,109.37 63.29,109.51 63.53,109.51 v2(63.66,109.38)
  L6_INT_2 w0.137: v2(72.91,110.82) 72.63,110.53 72.48,110.39 70.17,110.39 69.68,110.87 68.83,110.87 68.35,111.35 67.1,111.35 66.55,110.8 65.08,110.8 v2(63.66,109.38) 62.81,109.38 62.72,109.46 60.69,109.46 60.61,109.39 59.97,109.39 59.76,109.17 59.54,109.17 59.32,109.39 59.18,109.39 58.85,109.06 58.64,109.06 58.55,109.15 58.55,109.3 58.46,109.39 58.38,109.39 58.38,109.38 58.21,109.38 58.12,109.29 58.12,108.98 57.98,108.84 57.85,108.84 57.67,109.02 57.67,109.51 57.42,109.76 57.15,109.76 56.83,110.08 v2(56.65,110.08)
DRAM_ODT1: length 56.2
  TOP w0.102: U7.AA14 v2(64.71,91.6)
  TOP w0.137: U8.J1 v2(73.66,109.97) ; U9.J1 57.08,109.62 57.66,109.04 57.66,108.44 57.54,108.32 57.07,108.32 56.77,108.61 v2(56.77,109.17)
  L6_INT_2 w0.137: v2(56.77,109.17) 56.41,109.17 56.27,109.03 56.27,108.77 56.41,108.63 57,108.63 57.54,108.09 58.28,108.09 58.29,108.09 58.41,108.09 58.59,108.28 59.18,108.28 59.26,108.36 60.12,108.36 60.35,108.59 60.92,108.59 61.01,108.68 62.22,108.68 62.99,107.91 v2(63.56,107.91) 64.68,107.91 65.34,108.56 65.34,109.04 65.77,109.47 65.77,109.75 66.07,110.05 66.7,110.05 67.35,110.7 67.99,110.7 68.56,110.14 69.57,110.14 69.95,109.76 70.16,109.55 73.28,109.55 73.38,109.65 73.38,109.69 v2(73.66,109.97)
  BOTTOM w0.102: v2(64.71,91.6) 64.71,92.09 61.62,95.19 61.62,95.43 62.54,96.35
  BOTTOM w0.137: v2(63.56,107.91) 63.2,107.91 62.76,108.36 62.76,109.39 62.62,109.52 62.39,109.52 61.75,108.88 61.75,108.77 62.42,108.1 62.42,107.86 62.88,107.39 63.44,107.39 63.69,107.14 63.69,104.71 63.55,104.57 63.36,104.57 63.17,104.76 63.17,106.77 63.05,106.89 62.88,106.89 62.7,106.7 62.7,104.51 61.97,103.79 61.97,103.62 61.55,103.2 61.55,102.85 61.69,102.71 61.69,101.79 61.84,101.64 61.84,99.57 62.14,99.27 62.14,99.01 62,98.87 62,98.62 62.84,97.77 62.84,97.28 62.54,96.97 62.54,96.35
DRAM_RAS_B: length 55
  TOP w0.102: U7.AB15 v2(64.71,92.66)
  TOP w0.137: U8.J3 71.68,109.62 v2(71.32,109.98) ; U9.J3 v2(54.15,110.02)
  L3_INT_1 w0.137: v2(64.14,108.86) 64.23,108.77 64.79,108.77 64.93,108.91 64.93,109.06 65.36,109.49 65.36,109.99 65.14,110.21 64.9,110.21 64.66,109.96 64.66,109.54 64.46,109.35 64.35,109.35 63.91,109.79 63.91,110.02 64.89,111.01 64.89,112.63 65,112.74 65.45,112.74 65.79,112.4 65.79,112.02 65.67,111.9 65.43,111.9 65.31,111.78 65.31,111.61 65.43,111.49 65.67,111.49 65.79,111.37 65.79,111.2 65.67,111.08 65.43,111.08 65.31,110.96 65.31,110.79 65.43,110.67 65.67,110.67 65.79,110.55 65.79,109.15 65.38,108.74 65.38,106.18 65.1,105.9 65.1,102.65 64.41,101.96 64.41,96.32 65.12,95.61 65.12,93.61 64.86,93.35 64.86,93.34 64.71,93.18 v2(64.71,92.66)
  L6_INT_2 w0.137: v2(54.15,110.02) 54.59,109.58 55.14,109.58 55.18,109.62 56.9,109.62 57.26,109.26 57.26,108.83 57.6,108.48 58.25,108.48 58.43,108.67 59.01,108.67 59.1,108.75 59.96,108.75 60.19,108.98 60.76,108.98 60.85,109.07 62.38,109.07 62.48,108.97 63.37,108.97 63.49,108.86 v2(64.14,108.86) 64.14,108.8 64.49,108.46 64.68,108.46 64.95,108.72 64.95,108.93 64.43,109.45 64.43,109.6 64.59,109.76 64.77,109.76 65.07,109.45 65.25,109.45 65.4,109.6 65.4,109.78 65.09,110.08 65.09,110.26 65.24,110.41 66.66,110.41 67.3,111.05 68.19,111.05 68.7,110.54 69.6,110.54 70.16,109.98 v2(71.32,109.98)
DRAM_RESET: length 58.2
  TOP w0.137: U7.AC22 v2(61.53,96.9) ; v2(72.2,115.94) 72.2,115.52 U8.T2 ; U9.T2 v2(54.95,115.62)
  L3_INT_1 w0.137: v2(60.98,117.18) 60.98,117.94 61.07,118.04 61.37,118.04 61.57,117.84 61.57,117.15 61.13,116.71 61.13,116.36 61.58,115.9 61.58,115.73 61.45,115.6 61.22,115.6 61.08,115.46 61.08,115.24 61.23,115.09 61.48,115.09 61.58,114.99 61.58,114.6 61.42,114.43 60.75,114.43 60.49,114.17 60.49,113.18 60.65,113.01 60.65,111.88 60.49,111.72 60.49,109.26 61.34,108.41 61.34,108.22 61.02,107.9 61.02,107.55 61.1,107.46 61.1,107.27 61.02,107.19 61.02,106.84 61.09,106.77 61.09,106.57 60.97,106.45 60.97,105.97 60.79,105.8 60.79,105.65 60.78,105.64 60.78,104.6 60.92,104.46 61.18,104.46 61.32,104.6 61.32,105.06 61.44,105.18 61.61,105.18 62.08,104.71 62.08,104.42 61.92,104.26 61.78,104.26 61.62,104.11 61.62,103.84 61.8,103.67 61.93,103.67 62.08,103.53 62.08,103.26 61.17,102.36 v2(61.17,101.46) 61.17,99.29 61.03,99.15 61.03,98.7 61.53,98.2 v2(61.53,96.9)
  L6_INT_2 w0.137: v2(54.95,115.62) 54.55,115.21 53.66,115.21 53.4,114.96 53.21,114.96 52.53,115.64 52.53,115.84 55.61,118.92 58.57,118.92 59.45,118.04 60.11,118.04 v2(60.98,117.18) 62.79,118.99 69.15,118.99 v2(72.2,115.94)
  BOTTOM w0.137: R116.1 61.18,100.69 61.18,101.46 v2(61.17,101.46)
DRAM_SDBA0: length 56.4
  TOP w0.102: U7.R22 v2(57.28,92.66)
  TOP w0.137: U8.M2 v2(72.11,112.42) ; v2(54.96,112.41) 55.18,112.41 55.18,112.41 55.38,112.42 57.61,112.42 57.74,112.28 57.74,111.72 57.56,111.54 56.58,111.54 56.51,111.61 55.98,111.61 55.58,112.02 U9.M2
  L6_INT_2 w0.137: v2(54.96,112.41) 55.36,112.41 55.36,112.42 57.26,112.42 57.43,112.59 60.72,112.59 61.04,112.9 61.31,112.9 61.45,113.04 v2(61.45,113.31) 61.56,113.42 62.22,113.42 62.74,112.9 63.64,112.9 65.49,114.75 66.1,114.75 66.31,114.54 68.84,114.54 70.55,112.82 71.71,112.82 v2(72.11,112.42)
  BOTTOM w0.137: v2(61.45,113.31) 61.45,112.56 61.61,112.4 61.61,112.1 61.25,111.74 60.96,111.74 58.72,113.97 58.53,113.97 58.39,113.84 58.39,113.55 59.14,112.8 59.14,112.63 59.01,112.49 58.8,112.49 58.69,112.61 58.49,112.61 58.28,112.4 58.28,111.07 58.39,110.96 58.39,109.71 59.2,108.9 59.2,102.18 57.07,100.05 57.07,94.16 56.78,93.87 56.78,93.7 57.28,93.19 v2(57.28,92.66)
DRAM_SDBA1: length 58.1
  TOP w0.102: U7.P22 v2(56.75,92.13)
  TOP w0.137: U9.N8 50.55,113.07 50.43,113.19 50.25,113.19 50.16,113.1 50.16,112.56 50.3,112.42 51.5,112.42 52.14,113.05 52.14,113.92 52.58,114.36 52.58,116.1 52.37,116.31 52.37,116.5 53.85,117.99 54.64,117.99 54.88,117.75 55.22,117.75 55.46,117.99 55.73,117.99 55.87,117.86 55.87,117.67 56.01,117.54 56.28,117.54 56.42,117.67 56.42,117.86 56.56,117.99 56.82,117.99 56.96,117.85 56.96,117.55 v2(57.07,117.44) 57.34,117.17 60.29,117.17 60.74,116.73 61.14,116.73 61.48,117.07 62.35,117.07 64.85,114.56 64.85,113.3 65.71,112.44 67.33,112.44 U8.N8
  L3_INT_1 w0.137: v2(56.75,92.13) 56.75,92.66 55.29,94.12 55.29,95 55.1,95.18 55.1,96 55.62,96.52 55.62,102.95 55.8,103.13 55.8,106.08 55.36,106.52 55.36,107.73 55.09,108 54.67,108 54.42,108.25 54.42,108.68 53.74,109.36 53.74,109.9 53.6,110.05 53.6,115.72 55.32,117.44 v2(57.07,117.44)
DRAM_SDBA2: length 55.5
  TOP w0.102: U7.N23 v2(55.69,92.13)
  TOP w0.137: U9.M3 v2(54.15,112.42) ; U8.M3 v2(71.31,112.42)
  L6_INT_2 w0.137: v2(71.31,112.42) 70.53,112.42 69.07,113.87 65.22,113.87 63.85,112.51 61.36,112.51 v2(61.11,112.25) 60.94,112.25 60.89,112.2 57.83,112.2 57.22,111.59 56.81,111.59 56.39,112.01 53.62,112.01 53.41,112.23 53.2,112.44 53.2,113.52 53.34,113.66 53.58,113.66 53.72,113.51 53.72,112.84 v2(54.15,112.42)
  BOTTOM w0.137: v2(61.11,112.25) 58.34,115.02 58.34,115.4 58.25,115.49 58.03,115.49 57.89,115.35 57.89,111.57 57.62,111.3 57.62,111.09 58.01,110.69 58.01,110.08 57.79,109.85 57.79,109.66 58.73,108.72 58.73,102.43 56.68,100.38 56.68,94.52 56.06,93.9 56.06,93.35 56.64,92.77 56.64,92.54 56.22,92.13 v2(55.69,92.13)
DRAM_SDCKE0: length 62.3
  TOP w0.102: v2(63.65,93.72) U7.AB17
  TOP w0.137: v2(62.54,101.68) 62.54,102.92 62.4,103.06 61.94,103.06 61.73,103.28 61.73,105.7 61.88,105.86 62.11,105.86 62.25,105.72 62.25,103.99 62.41,103.83 62.59,103.83 62.73,103.96 62.73,106.93 R118.1 62.73,106.94 62.73,109.19 62.74,109.2 62.74,109.31 61.92,110.13 61.92,111.58 61.66,111.84 61.66,112.29 62.07,112.7 v2(62.07,112.96) ; v2(62.07,112.96) 61.69,112.96 61.53,112.8 61.19,112.8 59.74,114.25 57.77,114.25 57.2,114.82 56.65,114.82 55.88,114.82 55.74,114.96 55.74,115.49 55.17,116.06 53.99,116.06 53.7,115.77 53.7,113.01 51.51,110.82 50.39,110.82 49.98,110.42 U9.K9 ; v2(62.07,112.96) 62.49,112.96 63.15,112.29 63.8,112.29 63.93,112.16 63.93,111.94 62.89,110.9 62.89,110.74 63.13,110.5 63.28,110.5 64.35,111.57 64.52,111.57 64.71,111.39 64.71,111.17 63.81,110.28 63.81,110.1 64.07,109.85 64.25,109.85 65.27,110.87 65.45,110.87 65.64,110.68 65.64,110.49 64.59,109.44 64.59,108.7 64.32,108.43 64.32,108.22 64.45,108.08 64.67,108.08 65.02,108.43 65.02,109.15 66.15,110.28 66.33,110.28 66.58,110.03 66.8,110.03 66.91,110.14 U8.K9
  L3_INT_1 w0.137: v2(63.65,93.72) 63.65,94.23 63.27,94.6 63.27,94.95 63.49,95.17 63.49,95.48 63.08,95.89 63.08,101.14 v2(62.54,101.68)
DRAM_SDCKE1: length 56
  TOP w0.102: U7.AB22 v2(60.99,96.37)
  TOP w0.137: U8.J9 66.91,109.53 65.88,108.51 65.88,107.96 65.74,107.82 65.55,107.82 65.41,107.96 65.41,108.75 v2(66.28,109.62) ; U9.J9 v2(50.15,110.01)
  L6_INT_2 w0.137: v2(50.15,110.01) 50.67,110.53 52.9,110.53 54.27,109.17 55.25,109.17 56.17,108.24 56.9,108.24 57.59,107.55 60.04,107.55 v2(60.56,108.07) 61.14,108.07 61.23,108.16 62,108.16 62.83,107.34 65,107.34 66.68,109.02 66.68,109.21 v2(66.28,109.62)
  BOTTOM w0.137: v2(60.56,108.07) 60.22,107.73 60.22,107.46 60.34,107.34 60.66,107.34 60.78,107.22 60.78,107.05 60.66,106.93 60.34,106.93 60.22,106.81 60.22,106.64 60.34,106.52 60.66,106.52 60.78,106.4 60.78,106.23 60.66,106.11 60.34,106.11 60.22,105.99 60.22,105.41 R117.1 60.22,104.52 60.22,101.84 58.01,99.63 58.01,96.51 58.19,96.33 58.38,96.33 58.52,96.47 58.52,99.44 58.69,99.61 58.88,99.61 59.05,99.44 59.05,97.19 59.13,97.12 59.36,97.12 59.58,97.33 59.58,100.51 59.71,100.65 59.91,100.65 60.04,100.51 60.04,97.68 60.31,97.41 60.48,97.41 60.99,96.9 v2(60.99,96.37)
DRAM_SDCLK0_N: length 56.9
  TOP w0.104: v2(61.44,107.01) 61.1,107.01 61.02,107.1 59.94,107.1 59.73,107.31 59.73,107.5 59.94,107.71 59.94,108.31 59.2,109.05 59.2,109.42 59.43,109.65 59.62,109.65 60.58,108.69 61.11,108.69 61.51,109.09 61.51,109.59 60.91,110.2 60.91,110.96 60.55,111.32 60.55,112.28 60.25,112.57 59.67,112.57 59.4,112.3 59.4,111.11 59.18,110.88 58.94,110.88 58.13,110.07 58.13,108.49 58.69,107.94 58.69,107.52 57.75,106.59 57.75,105.73 58.25,105.23 59.4,105.23 59.66,104.98 59.66,103.62 R618.2 ; v2(70.44,109.06) 70.09,109.06 69.01,110.15 68.78,110.15 U8.K7 ; U9.K7 51.68,110.42 51.86,110.24 52.03,110.24 52.36,109.92 v2(52.59,109.92)
  L6_INT_2 w0.117: v2(52.59,109.92) 52.59,109.61 53.27,108.92 53.27,108.39 54.17,107.5 54.17,106.56 54.3,106.43 58.06,106.43 58.92,105.57 59.39,105.57 60.69,106.86 61.29,106.86 v2(61.44,107.01) 61.75,106.71 62.67,106.71 63.08,106.3 64.93,106.3 66.16,107.52 66.75,107.52 66.9,107.68 66.9,108.23 68.19,109.51 68.42,109.51 68.71,109.8 69.32,109.8 70.06,109.06 v2(70.44,109.06)
  BOTTOM w0.104: v2(70.44,109.06) 70.35,109.15 70.35,110.05 R90.2 70.3,111.39 TP23.1 ; 52.4,110.62 52.4,110.62 52.4,110.62 ; 52.4,110.62 52.4,112.02 TP24.1 ; 52.4,110.62 52.4,110.11 v2(52.59,109.92)
DRAM_SDCLK0_P: length 55.8
  TOP w0.104: R617.2 59.94,103.57 59.94,105.09 59.52,105.51 58.36,105.51 58.03,105.84 58.03,106.47 58.97,107.41 58.97,108.06 58.41,108.61 58.41,109.96 59.06,110.6 59.3,110.6 59.68,110.99 59.68,112.19 59.79,112.29 60.14,112.29 60.27,112.16 60.27,111.2 60.63,110.84 60.63,110.09 61.23,109.48 61.23,109.21 60.99,108.97 60.69,108.97 59.73,109.93 59.32,109.93 58.92,109.54 58.92,108.93 59.66,108.2 59.66,107.82 59.45,107.62 59.45,107.19 59.83,106.82 60.85,106.82 v2(61.39,106.28) ; v2(52.12,109.49) 52.12,109.76 51.92,109.96 51.74,109.96 51.7,109.96 U9.J7 ; v2(69.93,108.54) 69.93,108.83 68.89,109.87 68.76,109.87 U8.J7
  L6_INT_2 w0.117: v2(69.93,108.54) 69.79,108.4 69.62,108.4 69.45,108.56 69.45,108.74 69.6,108.89 69.6,109.13 69.2,109.52 68.83,109.52 68.53,109.23 68.31,109.23 67.18,108.11 67.18,107.56 66.87,107.25 66.28,107.25 65.05,106.02 62.97,106.02 62.56,106.43 61.54,106.43 v2(61.39,106.28) 61.08,106.58 60.8,106.58 59.51,105.29 58.8,105.29 57.94,106.15 54.19,106.15 53.89,106.45 53.89,107.38 52.99,108.28 52.99,108.81 52.31,109.49 52.12,109.49 v2(52.12,109.49)
  BOTTOM w0.104: v2(52.12,109.49) 51.71,109.9 R91.1 51.68,109.97 TP22.1 ; v2(69.93,108.54) 69.62,108.85 R90.1 69.62,109.85 TP21.1
DRAM_SDQS0_N: length 12.7
  TOP w0.102: U7.AD21 62.59,96.9 63.05,97.36
  TOP w0.104: U8.B7 68.78,104.28 68.99,104.28 69.24,104.03 69.24,102.95 69.07,102.79 68.86,102.79 68.33,102.25 TP42.1 68.33,102.04 68.15,101.86 67.9,101.62 67.17,101.62 66.79,101.23 66.33,101.23 66.06,100.96 66.06,100.5 65.95,100.4 65.5,100.4 65.22,100.12 65.22,99.67 65.11,99.56 64.66,99.56 64.29,99.19 TP41.1 64.29,98.73 63.05,97.49 63.05,97.36
DRAM_SDQS0_P: length 12.8
  TOP w0.102: 63.36,97.26 63.36,97.15 U7.AE21
  TOP w0.104: 63.36,97.26 63.36,97.41 63.47,97.52 63.75,97.52 64,97.76 TP43.1 64,98.04 64.67,98.71 64.67,99.17 64.77,99.28 65.23,99.28 65.5,99.55 65.5,100.01 65.61,100.12 66.07,100.12 66.34,100.39 66.34,100.84 66.45,100.95 66.9,100.95 67.29,101.34 67.86,101.34 TP40.1 67.96,101.28 68.17,101.49 68.7,102.02 68.7,102.23 68.98,102.51 69.19,102.51 69.52,102.84 69.52,104.15 69.1,104.56 68.76,104.56 U8.C7
DRAM_SDQS1_N: length 18.5
  TOP w0.104: U8.G3 71.71,107.75 71.55,107.59 71.31,107.59 v2(71.09,107.82) ; v2(68.18,96.29) 68.18,95.97 67.48,95.28 67.48,94.9 U7.AE15
  L3_INT_1 w0.117: v2(71.09,107.82) 71.09,107.68 70.67,107.25 70.67,106.59 70.51,106.44 70.51,105.54 70.03,105.05 70.03,104.61 70.3,104.34 70.54,104.34 70.65,104.24 70.65,104.04 70.55,103.95 70.4,103.95 70.15,103.7 70.15,103.1 70.42,102.84 70.42,102.7 70.07,102.35 70.07,101.88 70.43,101.52 70.43,100.42 69.11,99.11 69.11,98.62 69.11,96.95 68.46,96.29 v2(68.18,96.29)
DRAM_SDQS1_P: length 18.6
  TOP w0.104: v2(68.68,95.79) 68.39,95.79 67.76,95.16 67.76,94.79 66.69,93.71 66.69,93.58 66.3,93.19 U7.AD15 ; v2(71.09,107.1) 71.3,107.31 71.61,107.31 U8.F3
  L3_INT_1 w0.117: v2(71.09,107.1) 70.95,106.96 70.95,106.47 70.79,106.32 70.79,105.42 70.31,104.94 70.31,104.73 70.42,104.62 70.66,104.62 70.92,104.35 70.92,103.93 70.67,103.67 70.51,103.67 70.43,103.59 70.43,103.22 70.7,102.95 70.7,102.58 70.35,102.24 70.35,101.99 70.71,101.64 70.71,100.31 69.39,98.99 69.39,98.62 69.39,96.83 68.68,96.12 v2(68.68,95.79)
DRAM_SDQS2_N: length 12.2
  TOP w0.102: 58.12,96.72 58.34,96.5 U7.Y25
  TOP w0.104: U9.B7 51.52,104.18 51.59,104.18 51.91,103.87 51.91,103.73 51.86,103.68 51.68,103.68 51.59,103.59 51.59,103.51 51.88,103.22 51.98,103.22 52.06,103.29 52.06,103.44 52.14,103.53 52.25,103.53 52.43,103.35 52.47,103.04 52.47,102.37 53.48,101.36 53.86,100.98 TP46.1 53.98,100.86 57.48,97.36 57.56,97.28 TP44.1 57.72,97.13 57.81,97.03 58.12,96.72
DRAM_SDQS2_P: length 12.2
  TOP w0.094: 51.95,104.22 U9.C7
  TOP w0.102: U7.Y24 58.68,96.49 58.62,96.59 58.53,96.72 58.42,96.83
  TOP w0.104: 51.95,104.22 52.69,103.47 52.75,103.06 52.75,102.5 53.01,102.24 53.77,101.47 TP47.1 53.92,101.33 57.01,98.24 57.16,98.09 TP45.1 57.28,97.97 57.43,97.82 58.42,96.83
DRAM_SDQS3_N: length 18.6
  TOP w0.104: v2(53.36,106.98) 53.5,106.98 54.03,107.5 54.22,107.5 54.55,107.82 U9.G3 ; U7.T25 56.08,94.25 54.71,95.63 53.14,97.19 v2(53.14,97.49)
  L3_INT_1 w0.117: v2(53.14,97.49) 52.62,97.49 52.52,97.58 52.52,97.82 52.14,98.19 52.14,98.38 52.5,98.74 52.5,99.18 52.25,99.43 52.07,99.43 51.97,99.54 51.97,99.68 52.07,99.78 52.25,99.78 52.5,100.03 52.5,100.43 52.45,100.48 52.24,100.69 52.08,100.69 51.97,100.79 51.97,100.94 52.09,101.07 52.26,101.07 52.5,101.31 52.5,105.12 53.22,105.84 53.39,105.84 53.61,106.07 53.61,106.73 v2(53.36,106.98)
DRAM_SDQS3_P: length 18.7
  TOP w0.104: 56.75,93.72 U7.T24 56.19,93.72 55.87,94.04 55.87,94.07 52.96,96.98 v2(52.64,96.98) ; v2(53.18,106.26) 53.45,106.53 53.49,106.53 54.17,107.22 U9.F3
  L3_INT_1 w0.117: v2(52.64,96.98) 52.24,97.38 52.24,97.7 51.86,98.08 51.86,98.49 52.22,98.85 52.22,99.06 52.13,99.15 51.96,99.15 51.69,99.42 51.69,99.54 51.69,99.8 51.96,100.06 52.14,100.06 52.22,100.15 52.22,100.31 52.17,100.36 52.13,100.41 51.96,100.41 51.69,100.68 51.69,101.06 51.98,101.35 52.14,101.35 52.22,101.43 52.22,105.24 53.18,106.2 v2(53.18,106.26)
DRAM_SDWE_B: length 54.9
  TOP w0.102: U7.AB14 v2(65.24,92.13)
  TOP w0.137: U9.L3 54.52,111.22 v2(54.12,111.62) ; U8.L3 v2(71.31,111.62)
  L3_INT_1 w0.137: v2(62.74,111.36) 62.57,111.19 62.57,110.92 62.71,110.78 62.92,110.78 63.52,111.37 63.52,111.59 63.4,111.7 63.4,111.86 63.58,112.04 63.58,112.67 62.28,113.97 62.09,113.97 61.95,113.83 61.95,113.68 62.54,113.09 62.54,112.81 62.72,112.63 63,112.63 63.15,112.48 63.15,112.27 63.01,112.14 62.77,112.14 62.57,111.93 62.57,111.84 62.36,111.63 62.11,111.63 61.87,111.39 61.87,111.14 61.68,110.95 61.68,110.69 61.93,110.44 61.93,110.23 62.18,109.98 62.18,109.81 62.04,109.67 61.91,109.67 61.6,109.98 61.46,109.98 61.27,109.79 61.27,109.58 62.34,108.52 62.34,105.56 62.86,105.04 62.86,102.75 61.98,101.87 61.98,101.1 62.56,100.52 62.56,96.35 62.21,96 62.21,95.69 62.44,95.46 62.44,95.17 62.12,94.85 62.12,94.7 62.43,94.39 62.43,94.39 63.26,93.55 63.27,93.55 64.69,92.13 v2(65.24,92.13)
  L6_INT_2 w0.137: v2(71.31,111.62) 70.32,111.62 68.81,113.13 66.3,113.13 65.88,112.71 65.2,112.71 64.2,111.7 63.08,111.7 v2(62.74,111.36) 62.68,111.3 62.54,111.3 62.46,111.22 61.97,111.22 61.62,110.87 61.21,110.87 60.71,111.38 59.81,111.38 59.68,111.25 59.68,110.94 59.32,110.59 58.07,110.59 57.77,110.88 55.46,110.88 55.12,111.22 54.52,111.22 v2(54.12,111.62)
DRAM_ZQ: length 2.8
  TOP w0.102: U7.AB13 v2(65.77,91.6)
  BOTTOM w0.104: v2(65.77,91.6) 65.77,92.14 66.2,92.57
  BOTTOM w0.137: 66.2,92.57 66.2,93.65 R86.2
EEPROM_I2C1_SCL: length 1.5
  TOP w0.137: R233.1 U41.6
EEPROM_I2C1_SDA: length 1.5
  TOP w0.137: R237.1 U41.5
EMI_GPIO3: length 1.6
  BOTTOM w0.127: Q41.2 11.48,80.26 10.95,79.73 R764.2
ENET_INT_B: length 112.3
  TOP w0.102: U7.M1 66.91,79.4 68.06,78.26
  TOP w0.127: v1(27.37,34.14) R688.1 R680.2 ; v1(62.7,31.24) v1(58.01,31.24) ; v1(70.05,78.26) 68.06,78.26
  BOTTOM w0.102: v1(70.05,78.26) 70.05,78.09
  BOTTOM w0.127: v1(62.7,31.24) 63.04,31.57 72.07,31.57 75.95,35.45 75.95,65.77 73.12,68.61 73.12,74.3 70.05,77.37 70.05,78.09 ; v1(58.01,31.24) 54.58,27.81 41.88,27.81 39.79,25.72 28.36,25.72 27.8,26.29 27.8,28.72 28.48,29.41 28.48,29.78 28.35,29.9 28.35,33.16 v1(27.37,34.14)
ENET_MDC: length 73.7
  TOP w0.137: R95.1 76.43,72.13 76.43,71.7 76.74,71.39 76.75,71.39 77.65,70.48 v1(77.69,70.48) ; U13.16 v1(40.48,33.29)
  L6_INT_2 w0.127: v1(77.69,70.48) 76.1,68.9 59.58,68.9 57.84,67.16 57.84,56.11 49.94,48.2 41.18,48.2 40.83,47.86 40.83,41.03 40.48,40.68 40.48,37.46 40.92,37.02 40.92,36.47 40.48,36.02 v1(40.48,33.29)
ENET_MDIO: length 72.9
  TOP w0.102: U7.R5 66.83,83.11 v2(66.83,83.11)
  TOP w0.137: U13.17 v1(39.96,33.79)
  L3_INT_1 w0.137: v2(66.83,83.11) 66.3,83.11 65.92,83.49 65.14,83.49 64.92,83.26 63.35,83.26 63.14,83.06 63.14,82.43 62.93,82.22 61.95,82.22 61.82,82.35 61.82,82.67 61.92,82.77 61.92,83.16 61.78,83.3 61.19,83.3 60.63,82.74 60.29,82.74 60.2,82.83 58.59,82.83 57.91,82.15 55.9,82.15 54.86,81.1 50.88,81.1 48.31,78.54 48.31,68.26 47.7,67.65 47.7,60.25 46.25,58.79 46.25,42.79 v1(46.1,42.64)
  BOTTOM w0.137: v1(39.96,33.79) 40.09,33.79 R129.2 40.84,34.54 41.62,34.54 43.85,36.77 43.85,40.39 v1(46.1,42.64)
